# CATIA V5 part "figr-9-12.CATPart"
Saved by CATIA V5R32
Part number: Part2
Bounding box of the stored display mesh (mm): x -96.75 to 0, y -83.031 to 83.031, z -58.031 to 58.031
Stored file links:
  D:\PROJECTS\Project 2022\CATIA V5 6R 2022\Resources\Part Files\c09_catia_v5_6r2022_prt\c09_catia_v5_6r2022_prt\figr-9-12.CATPart
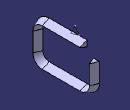
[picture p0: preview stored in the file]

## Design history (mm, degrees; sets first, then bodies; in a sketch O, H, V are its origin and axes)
Body1 (main body)
  Sketch1 on yz-plane, origin (0, 0, 0), H (0, 1, 0), V (0, 0, 1)
    point P1 (-75, 50)
    line L1 (-50, 50) -> (50, 50)
    line L2 (75, 25) -> (75, -25)
    line L3 (50, -50) -> (-50, -50)
    line L4 (-75, -25) -> (-75, 25)
    point P2 (75, 50)
    point P3 (75, -50)
    arc A1 centre (-50, 25) radius 25 from (-50, 50) to (-75, 25) ccw
    arc A2 centre (-50, -25) radius 25 from (-50, -50) to (-75, -25) cw
    arc A3 centre (50, -25) radius 25 from (50, -50) to (75, -25) ccw
    distance V L4 = 75
    distance H L1 = 50
    distance P1 P2 = 150
    radius A1 = 25
    radius A2 = 25
    distance P2 P3 = 100
    radius A3 = 25
    horizontal: L1 H, L3 H
    vertical: L2 V, L4 V
    coincidence: L1 P1, L4 P1, L3 P3, L2 P3, L2 P2, L1 P2
    tangency: A1 L1, A1 L4, A2 L3, A2 L4, A3 L3, A3 L2
  Plane1: type Angle, RefPlane yz-plane, Direction Sketch1.V, Angle 31
  Plane2: type Offset, RefPlane Plane1, Offset -108
  Sketch2 on Plane2, origin (-92.5741, -55.6241, 0), H (-0.515, 0.8572, 0), V (0, 0, 1)
    line L1 (0, 0) -> (-8.0309, -18.5626)
    line L2 (-8.0309, -18.5626) -> (8.1085, -18.5626)
    line L3 (8.1085, -18.5626) -> (0, 0)
    horizontal: L2 H
  Rib1: profile Sketch2, centre curve Sketch1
